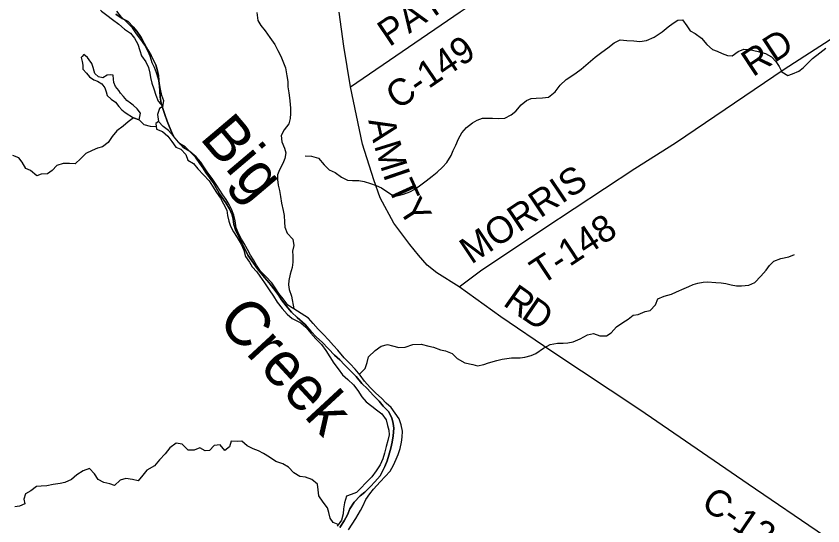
# Model space of a CAD drawing. Extents: x 114843 to 284848, y 317643 to 566895.
# Drawn here: x 132825 to 141921, y 394917 to 400664 of the extents above; entities that cross this region are included whole.
import ezdxf

# ---------------------------------------------------------------- set-up
doc = ezdxf.new("R2010")
doc.units = 0
for name, color, linetype in [('GM_X_County', 7, 'Continuous'), ('GM_X_County_Road', 7, 'Continuous'), ('GM_X_County_Road_Text', 7, 'Continuous'), ('GM_X_Major_River', 7, 'Continuous'), ('GM_X_Major_River_Text', 7, 'Continuous'), ('GM_X_Minor_Lake', 7, 'Continuous'), ('GM_X_Minor_River', 7, 'Continuous'), ('GM_X_Township', 7, 'Continuous'), ('GM_X_Township_Road', 7, 'Continuous'), ('GM_X_Township_Road_Text', 7, 'Continuous')]:
    doc.layers.add(name, color=color, linetype=linetype)

msp = doc.modelspace()

# ---------------------------------------------------------------- linework, layer by layer
at = {"layer": 'GM_X_County'}
for points in [[(133950.4, 400685.6), (134020.3, 400638.9), (134086.2, 400602.2), (134143.9, 400543.5), (134185.6, 400493), (134233.1, 400422.4), (134268.7, 400359.8), (134308.2, 400285.3), (134347.7, 400218.7), (134375.4, 400166.3), (134399, 400113.9), (134414.6, 400061.6), (134428.1, 399995.2), (134435.6, 399937), (134441.1, 399874.7), (134444.6, 399822.5), (134448, 399750.2), (134459.5, 399681.8), (134477, 399621.5), (134502.5, 399555), (134527.9, 399478.5), (134551.5, 399424.1), (134579, 399351.7), (134610.6, 399293.2), (134666.2, 399228.5), (134732.1, 399189.8), (134787.8, 399135.2), (134847.5, 399072.5), (134897.1, 399003.8), (134934.4, 398951.7), (134964.5, 398900.7), (135044.8, 398787.2), (135118.4, 398662), (135188.6, 398558.3), (135230.5, 398490.9), (135259.1, 398423.2), (135272.7, 398373.7), (135279.7, 398314.3), (135301.7, 398245), (135378.9, 398092.5), (135437.7, 397970.6), (135546.3, 397815.9), (135626.5, 397715.7), (135678, 397656.6), (135731.6, 397589.9), (135779.2, 397525.3), (135816.8, 397464.7), (135870.4, 397398.1), (135928, 397327.3), (135993.7, 397266.6), (136083.3, 397188.3), (136147.7, 397112.1), (136212.2, 397046), (136276.6, 396988), (136345.1, 396913.8), (136415.5, 396841.7), (136473.9, 396787.7), (136526.3, 396731.6), (136596.7, 396659.5), (136657.2, 396599.4), (136723.6, 396521.3), (136786, 396461.2), (136850.5, 396391), (136918.9, 396321), (136961.2, 396266.8), (137023.6, 396204.7), (137059.9, 396136.6), (137076.1, 396070.4), (137082.2, 396018.2), (137076.2, 395931.8), (137064.3, 395861.5), (137050.3, 395793.3), (137028.3, 395714.9), (137008.2, 395650.6), (136982.2, 395584.3), (136956.1, 395532), (136928, 395479.8), (136867.8, 395411.4), (136819.6, 395359), (136755.3, 395296.6), (136705.1, 395256.4), (136634.8, 395183.9), (136586.6, 395107.5), (136560.5, 395041.2), (136524.4, 394972.9), (136476.3, 394896.5)], [(136476.3, 394896.5), (136524.4, 394972.9), (136560.5, 395041.2), (136586.6, 395107.5), (136634.8, 395183.9), (136705.1, 395256.4), (136755.3, 395296.6), (136819.6, 395359), (136867.8, 395411.4), (136928, 395479.8), (136956.1, 395532), (136982.2, 395584.3), (137008.2, 395650.6), (137028.3, 395714.9), (137050.3, 395793.3), (137064.3, 395861.5), (137076.2, 395931.8), (137082.2, 396018.2), (137076.1, 396070.4), (137059.9, 396136.6), (137023.6, 396204.7), (136961.2, 396266.8), (136918.9, 396321), (136850.5, 396391), (136786, 396461.2), (136723.6, 396521.3), (136657.2, 396599.4), (136596.7, 396659.5), (136526.3, 396731.6), (136473.9, 396787.7), (136415.5, 396841.7), (136345.1, 396913.8), (136276.6, 396988), (136212.2, 397046), (136147.7, 397112.1), (136083.3, 397188.3), (135993.7, 397266.6), (135928, 397327.3), (135870.4, 397398.1), (135816.8, 397464.7), (135779.2, 397525.3), (135731.6, 397589.9), (135678, 397656.6), (135626.5, 397715.7), (135546.3, 397815.9), (135437.7, 397970.6), (135378.9, 398092.5), (135301.7, 398245), (135279.7, 398314.3), (135272.7, 398373.7), (135259.1, 398423.2), (135230.5, 398490.9), (135188.6, 398558.3), (135118.4, 398662), (135044.8, 398787.2), (134964.5, 398900.7), (134934.4, 398951.7), (134897.1, 399003.8), (134847.5, 399072.5), (134787.8, 399135.2), (134732.1, 399189.8), (134666.2, 399228.5), (134610.6, 399293.2), (134579, 399351.7), (134551.5, 399424.1), (134527.9, 399478.5), (134502.5, 399555), (134477, 399621.5), (134459.5, 399681.8), (134448, 399750.2), (134444.6, 399822.5), (134441.1, 399874.7), (134435.6, 399937), (134428.1, 399995.2), (134414.6, 400061.6), (134399, 400113.9), (134375.4, 400166.3), (134347.7, 400218.7), (134308.2, 400285.3), (134268.7, 400359.8), (134233.1, 400422.4), (134185.6, 400493), (134143.9, 400543.5), (134086.2, 400602.2), (134020.3, 400638.9), (133950.4, 400685.6)]]:
    msp.add_lwpolyline(points, dxfattribs=at)
at = {"layer": 'GM_X_County_Road'}
for points in [[(136594.3, 399866), (137829.4, 400711.5), (141179, 402947.6), (141215, 402965.7), (141241.1, 402967.7), (141261.1, 402963.7), (141281.1, 402951.7), (141313.1, 402913.6), (141487.4, 402620.9), (141509.4, 402586.8), (141529.5, 402576.8), (141559.5, 402580.9), (141689.6, 402661.2), (144712.9, 404666.2), (146657, 405975.2)], [(141938.1, 394800.8), (141080, 395387.2), (139857.3, 396226.3), (138865.5, 396883.5), (138291.1, 397274.8), (137819, 397611.5), (137569.2, 397769.1), (137460.2, 397857.6), (137361.7, 397967.5), (137265.2, 398087.9), (137083.9, 398327.9), (136928.8, 398615.9), (136859.3, 398819.5), (136731.5, 399219.5), (136594.3, 399866), (136518.1, 400325), (136466.8, 400710.6)]]:
    msp.add_lwpolyline(points, dxfattribs=at)
at = {"layer": 'GM_X_Major_River'}
for points in [[(133775.9, 400731.6), (133787.3, 400721), (133848.4, 400673.6), (133912, 400627.1), (133983.6, 400572.4), (134047.1, 400515.9), (134112.8, 400473.3), (134160.4, 400416.9), (134197.8, 400346.5), (134219.3, 400278.2), (134238.8, 400215.9), (134288.2, 400149.4), (134315.7, 400085.1), (134333.2, 400020.9), (134340.8, 399970.7), (134356.3, 399908.5), (134377.8, 399844.2), (134401.3, 399773.9), (134426.7, 399705.6), (134478.3, 399645.1)], [(134478.3, 399645.1), (134490.8, 399709.2), (134467.2, 399769.4), (134453.8, 399839.7), (134442.3, 399903.9), (134428.7, 399954), (134407.3, 400026.3), (134383.7, 400086.6), (134360.1, 400136.9), (134336.7, 400211.2), (134309.2, 400271.5), (134275.7, 400335.9), (134232.2, 400402.3), (134180.7, 400462.8), (134137.3, 400533.2), (134075.8, 400593.8), (134012.2, 400652.4), (133960.8, 400720.9)], [(134478.3, 399645.1), (134442.1, 399623.4), (134417.5, 399553.4), (134428.9, 399475.2)], [(134428.9, 399475.2), (134398.8, 399455.4)], [(134398.8, 399455.4), (134406.2, 399389.2), (134474, 399362.7), (134535.6, 399312.1), (134581.1, 399251.7), (134626.6, 399185.2), (134682.4, 399162.8), (134738, 399104.3), (134761.5, 399040), (134823.2, 399003.4), (134872.7, 398941), (134936.2, 398876.4), (135001.6, 398807.8), (135037.1, 398747.4), (135084.6, 398674.9), (135128, 398610.5), (135163.5, 398546.1), (135199, 398477.7), (135208.5, 398415.5), (135224, 398351.3), (135241.6, 398297.1), (135275, 398230.7), (135316.5, 398168.3), (135363.9, 398091.8), (135391.4, 398023.5), (135410.9, 397955.2), (135456.3, 397888.8), (135487.9, 397838.5), (135539.5, 397782), (135571.1, 397731.6), (135624.5, 397657.1), (135677.9, 397578.6), (135725.3, 397508.1), (135766.7, 397437.7), (135824.2, 397369.1), (135881.7, 397304.6), (135935.3, 397256.1), (136033.5, 397207.5)], [(136119.6, 397259.4), (135954.2, 397364.2), (135886.5, 397406.7), (135835, 397475.2), (135787.5, 397537.7), (135746, 397600.1), (135706.5, 397656.5), (135645, 397723.1), (135581.5, 397789.7), (135534.1, 397856.1), (135500.5, 397914.5), (135467, 397970.8), (135433.5, 398033.2), (135396, 398099.6), (135366.4, 398149.9), (135336.8, 398206.2), (135307.4, 398278.6), (135294, 398354.8), (135280.5, 398419), (135253.1, 398487.3), (135225.5, 398539.6), (135191.9, 398598), (135154.4, 398650.4), (135122.8, 398700.7), (135089.2, 398755), (135035.8, 398831.6), (134986.3, 398898), (134940.8, 398964.5), (134907.3, 399016.8), (134853.8, 399079.4), (134784.2, 399136), (134712.6, 399178.6), (134655.1, 399243.1), (134597.6, 399309.7), (134544.1, 399376.2), (134482.5, 399420.7), (134428.9, 399475.2)], [(136570.9, 394872.4), (136655.1, 394998.4), (136707.3, 395088.4), (136733.4, 395140.4), (136767.6, 395212.5), (136811.7, 395276.5), (136855.8, 395330.5), (136929.9, 395412.5), (136986, 395474.5), (137042.2, 395532.5), (137078.3, 395600.5), (137108.4, 395668.5), (137130.5, 395720.6), (137154.6, 395790.6), (137170.8, 395858.7), (137178.9, 395918.7), (137181, 395984.8), (137167.2, 396056.9), (137145.3, 396123), (137097.4, 396189.1), (137053.5, 396251.2), (136995.6, 396301.3), (136943.8, 396355.5), (136881.9, 396413.6), (136818, 396475.7), (136754.1, 396549.9), (136704.3, 396616), (136646.4, 396682.2), (136592.5, 396742.3), (136522.7, 396812.5), (136452.8, 396896.6), (136404.9, 396950.8), (136345.1, 397014.9), (136291.2, 397073), (136231.3, 397133.2), (136175.4, 397197.3), (136119.6, 397259.4)], [(136033.5, 397207.5), (136091.4, 397155.4), (136147.2, 397089.2), (136205.1, 397027.1), (136269, 396962.9), (136316.8, 396892.8), (136408.6, 396752.6), (136454.4, 396688.4), (136506.3, 396620.3), (136566.2, 396566.2), (136628.1, 396506), (136675.9, 396441.9), (136723.8, 396369.8), (136771.7, 396315.6), (136835.6, 396265.5), (136887.5, 396223.4), (136949.4, 396179.3), (136995.3, 396111.1), (137013.1, 396047), (137025.1, 395997), (137030.9, 395944.9), (137016.8, 395878.9), (136996.7, 395810.8), (136978.6, 395736.8), (136960.4, 395670.7), (136928.3, 395606.7), (136884.2, 395538.7), (136836.1, 395468.7), (136763.9, 395396.7), (136713.8, 395346.7), (136663.7, 395294.7), (136601.7, 395268.7), (136549.7, 395250.8), (136527.5, 395174.7), (136515.4, 395108.7), (136511.3, 395052.6), (136495.1, 394982.6), (136443, 394912.6)]]:
    msp.add_lwpolyline(points, dxfattribs=at)
at = {"layer": 'GM_X_Minor_Lake'}
msp.add_line((134147.8, 399516.3), (134211.8, 399496.2), dxfattribs=at)
for points in [[(134211.8, 399496.2), (134227.8, 399570.3), (134189.9, 399620.4), (134145.9, 399660.5), (134115.9, 399682.5), (134074, 399714.6), (134036, 399756.7), (134000.1, 399796.7), (133982.1, 399826.8), (133946.2, 399870.9), (133926.2, 399914.9), (133922.2, 399955), (133920.2, 399997.1), (133892.3, 400001.1), (133850.3, 399999.1), (133802.3, 399967.1), (133752.3, 399981.1), (133712.4, 400017.2), (133704.4, 400043.2), (133694.4, 400085.3), (133678.5, 400129.3), (133648.5, 400171.4), (133630.5, 400199.5), (133586.6, 400231.5), (133567.9, 400210.1)], [(133567.9, 400210.1), (133558.6, 400199.5), (133570.5, 400151.4), (133576.5, 400111.4), (133578.5, 400067.3), (133616.4, 400021.2), (133650.4, 399979.1), (133702.3, 399947.1), (133742.3, 399931), (133792.3, 399899), (133826.2, 399856.9), (133840.2, 399810.8), (133850.1, 399770.8), (133898.1, 399728.7), (133944, 399694.6), (133982, 399646.5), (134015.9, 399606.5), (134055.9, 399578.4), (134147.8, 399516.3)], [(134478.3, 399645.1), (134442.1, 399623.4), (134417.5, 399553.4), (134428.9, 399475.2)]]:
    msp.add_lwpolyline(points, dxfattribs=at)
at = {"layer": 'GM_X_Minor_River'}
for points in [[(135537.9, 400706.4), (135550.2, 400614.4), (135582.1, 400560.2), (135631.9, 400499.9), (135683.7, 400421.6), (135743.5, 400345.3), (135777.3, 400277.1), (135811.1, 400212.8), (135840.9, 400136.6), (135862.7, 400082.4), (135878.5, 399992.2), (135888.3, 399928), (135888.1, 399867.9), (135897.9, 399797.7), (135905.8, 399743.6), (135915.6, 399671.4), (135917.4, 399621.3), (135917.3, 399567.1), (135913.1, 399511), (135898.9, 399450.9), (135846.7, 399380.9), (135814.6, 399316.8), (135822.4, 399248.6), (135850.2, 399174.4), (135866, 399122.2), (135855.8, 399058.1), (135833.7, 399004.1), (135793.5, 398930), (135773.3, 398875.9), (135773.2, 398823.8), (135781, 398759.6), (135792.8, 398699.4), (135804.6, 398631.3), (135818.4, 398557.1), (135836.2, 398470.8), (135846, 398416.7), (135849.8, 398340.5), (135853.7, 398286.4), (135879.5, 398218.2), (135943.3, 398147.8), (135955.1, 398077.7), (135940.9, 398013.5), (135942.7, 397961.4), (135944.5, 397891.3), (135936.4, 397831.1), (135914.2, 397755), (135900, 397684.9), (135895.8, 397632.8), (135903.7, 397580.7), (135929.5, 397506.4), (135954.2, 397364.2)], [(136083, 399087.7), (136155, 399083.5), (136235, 399061.1), (136298.6, 398986.8), (136354.4, 398930.5), (136422.3, 398900.2), (136492.1, 398847.9), (136559.9, 398813.6), (136615.9, 398809.3), (136689.9, 398809.1), (136749.9, 398800.8), (136821.8, 398778.5), (136885.7, 398756.3), (136943.6, 398730), (137005.5, 398687.7), (137057.3, 398651.5), (137115.3, 398639.2), (137193.3, 398655), (137265.5, 398682.7), (137319.7, 398714.6), (137371.8, 398750.4), (137446.1, 398806.2), (137516.3, 398858), (137572.5, 398905.9), (137632.8, 398959.7), (137679.1, 399015.6), (137729.4, 399091.5), (137751.7, 399149.5), (137781.9, 399209.5), (137812.2, 399279.5), (137848.6, 399347.4), (137900.8, 399409.3), (137971.1, 399461.1), (138021.2, 399491), (138083.3, 399512.8), (138145.4, 399514.5), (138197.4, 399514.3), (138265.4, 399510.1), (138335.4, 399513.8), (138405.6, 399549.6), (138457.8, 399593.5), (138520.1, 399663.3), (138580.3, 399711.2), (138632.4, 399735), (138688.5, 399738.8), (138758.5, 399742.5), (138828.5, 399752.3), (138900.8, 399810.1), (138957.2, 399884), (139025.5, 399949.8), (139079.6, 399981.7), (139139.8, 400023.5), (139194, 400065.3), (139276.3, 400133.1), (139354.7, 400202.9), (139428.9, 400256.7), (139497.2, 400308.5), (139569.4, 400362.3), (139635.6, 400398.1), (139711.6, 400389.8), (139787.5, 400385.5), (139857.5, 400377.3), (139931.6, 400391), (140017.8, 400428.7), (140108.1, 400486.5), (140178.3, 400542.3), (140232.5, 400586.1), (140286.7, 400620), (140338.7, 400621.8), (140386.4, 400553.5), (140424.2, 400499.3), (140482.1, 400467), (140553.8, 400416.7), (140611.5, 400344.4), (140677.3, 400286.1), (140729.2, 400269.8), (140785.1, 400241.6), (140845, 400219.3), (140897, 400215.1), (140967.3, 400266.9), (141031.4, 400292.7), (141093.4, 400286.5), (141191.3, 400266.1), (141273.2, 400243.7), (141343.1, 400203.4), (141390.8, 400151.2), (141428.6, 400097), (141458.3, 400036.8), (141526.2, 399994.4), (141578.3, 400012.3), (141648.4, 400044.1), (141698.6, 400081.9), (141752.8, 400133.8), (141805.1, 400185.6), (141887.4, 400249.4), (141955.6, 400301.2)], [(134403.4, 399414.5), (134339.6, 399420.1), (134267.7, 399440.1), (134211.8, 399496.2), (134147.8, 399516.3), (134089.8, 399474.2), (134031.8, 399422.2), (133961.8, 399370.1), (133907.8, 399306), (133863.8, 399240), (133799.8, 399191.9), (133743.8, 399173.9), (133681.9, 399147.9), (133609.9, 399115.8), (133553.9, 399059.8), (133491.9, 398999.7), (133425.9, 399001.7), (133354, 399001.8), (133284, 398981.8), (133230, 398923.7), (133180, 398887.7), (133108, 398883.7), (133058, 398863.7), (132988.1, 398921.8), (132934.2, 398947.8), (132894.2, 399015.9), (132856.3, 399068), (132786.3, 399092.1)], [(136695.4, 396626.1), (136760.6, 396689.9), (136780.9, 396757.9), (136797.2, 396822), (136873.5, 396895.8), (136941.7, 396943.6), (137011.8, 396961.4), (137069.7, 396945.1), (137139.7, 396926.8), (137209.7, 396932.6), (137297.9, 396960.3), (137389.9, 396963.9), (137479.8, 396943.6), (137531.8, 396933.4), (137609.7, 396901), (137667.6, 396890.8), (137739.5, 396860.5), (137799.3, 396802.2), (137883.1, 396753.8), (137973, 396737.4), (138027, 396721.2), (138097, 396735), (138149.1, 396756.8), (138245.3, 396782.5), (138305.3, 396796.2), (138357.4, 396804.1), (138411.4, 396809.9), (138507.4, 396811.5), (138561.5, 396819.3), (138631.6, 396837.1), (138683.7, 396860.9), (138770, 396920.7), (138844.2, 396960.4), (138928.3, 396978.1), (138994.3, 396977.9), (139044.3, 396979.7), (139106.4, 396993.5), (139184.5, 397027.2), (139266.7, 397069), (139334.8, 397086.8), (139406.7, 397058.4), (139482.8, 397060.2), (139532.9, 397092), (139595.2, 397159.9), (139665.5, 397209.7), (139725.6, 397247.5), (139781.8, 397293.4), (139837.9, 397299.2), (139916, 397332.9), (139974.1, 397344.7), (140034.4, 397410.6), (140060.7, 397476.5), (140132.9, 397508.3), (140213, 397528), (140271.1, 397553.9), (140355.3, 397591.6), (140409.4, 397617.4), (140459.5, 397639.3), (140509.6, 397655.1), (140569.7, 397664.9), (140621.7, 397666.7), (140715.7, 397660.3), (140773.7, 397656.1), (140827.6, 397647.9), (140887.6, 397635.7), (140945.5, 397623.4), (141001.6, 397623.2), (141087.6, 397630.9), (141151.8, 397660.7), (141222.1, 397730.5), (141282.4, 397800.4), (141318.6, 397852.3), (141368.9, 397900.2), (141447, 397931.9), (141535.1, 397951.7), (141601.2, 397975.4)], [(136024.2, 395473.6), (135956.3, 395513.7), (135894.4, 395579.8), (135830.4, 395615.9), (135754.5, 395643.9), (135682.6, 395690), (135614.6, 395732.1), (135558.7, 395764.2), (135498.7, 395784.2), (135428.8, 395820.3), (135370.8, 395870.4), (135316.9, 395866.4), (135250.9, 395870.5), (135230.9, 395806.4), (135178.9, 395768.3), (135125, 395830.4), (135059, 395824.4), (135005, 395768.4), (134955, 395762.4), (134895.1, 395798.4), (134833.1, 395770.4), (134763.1, 395770.5), (134697.2, 395838.6), (134627.3, 395848.6), (134559.3, 395796.6), (134503.3, 395730.5), (134441.2, 395662.4), (134383.2, 395594.3), (134299.3, 395546.3), (134253.3, 395490.2), (134201.2, 395424.1), (134135.3, 395438.2), (134063.3, 395452.2), (133999.4, 395430.2), (133933.4, 395370.1), (133881.4, 395390.2), (133813.5, 395406.2), (133749.5, 395438.3), (133709.6, 395504.4), (133651.6, 395562.5), (133581.7, 395538.5), (133509.7, 395490.5), (133447.7, 395438.4), (133373.7, 395406.4), (133321.7, 395394.4), (133241.8, 395382.4), (133169.8, 395366.4), (133105.8, 395364.4), (133053.9, 395362.4), (132991.9, 395310.4), (132929.9, 395276.3), (132909.8, 395218.3), (132923.8, 395166.2), (132863.8, 395138.2), (132811.8, 395130.2)], [(136456.4, 394930.6), (136398.4, 394954.4), (136366.2, 395004.3), (136349.9, 395066.3), (136335.7, 395118.3), (136285.5, 395184.1), (136239.2, 395254), (136230.9, 395322), (136222.6, 395388), (136158.4, 395437.7), (136088.2, 395467.4), (136024.2, 395473.6)]]:
    msp.add_lwpolyline(points, dxfattribs=at)
at = {"layer": 'GM_X_Township'}
for points in [[(133950.4, 400685.6), (134020.3, 400638.9), (134086.2, 400602.2), (134143.9, 400543.5), (134185.6, 400493), (134233.1, 400422.4), (134268.7, 400359.8), (134308.2, 400285.3), (134347.7, 400218.7), (134375.4, 400166.3), (134399, 400113.9), (134414.6, 400061.6), (134428.1, 399995.2), (134435.6, 399937), (134441.1, 399874.7), (134444.6, 399822.5), (134448, 399750.2), (134459.5, 399681.8), (134477, 399621.5), (134502.5, 399555), (134527.9, 399478.5), (134551.5, 399424.1), (134579, 399351.7), (134610.6, 399293.2), (134666.2, 399228.5), (134732.1, 399189.8), (134787.8, 399135.2), (134847.5, 399072.5), (134897.1, 399003.8), (134934.4, 398951.7), (134964.5, 398900.7), (135044.8, 398787.2), (135118.4, 398662), (135188.6, 398558.3), (135230.5, 398490.9), (135259.1, 398423.2), (135272.7, 398373.7), (135279.7, 398314.3), (135301.7, 398245), (135378.9, 398092.5), (135437.7, 397970.6), (135546.3, 397815.9), (135626.5, 397715.7), (135678, 397656.6), (135731.6, 397589.9), (135779.2, 397525.3), (135816.8, 397464.7), (135870.4, 397398.1), (135928, 397327.3), (135993.7, 397266.6), (136083.3, 397188.3), (136147.7, 397112.1), (136212.2, 397046), (136276.6, 396988), (136345.1, 396913.8), (136415.5, 396841.7), (136473.9, 396787.7), (136526.3, 396731.6), (136596.7, 396659.5), (136657.2, 396599.4), (136723.6, 396521.3), (136786, 396461.2), (136850.5, 396391), (136918.9, 396321), (136961.2, 396266.8), (137023.6, 396204.7), (137059.9, 396136.6), (137076.1, 396070.4), (137082.2, 396018.2), (137076.2, 395931.8), (137064.3, 395861.5), (137050.3, 395793.3), (137028.3, 395714.9), (137008.2, 395650.6), (136982.2, 395584.3), (136956.1, 395532), (136928, 395479.8), (136867.8, 395411.4), (136819.6, 395359), (136755.3, 395296.6), (136705.1, 395256.4), (136634.8, 395183.9), (136586.6, 395107.5), (136560.5, 395041.2), (136524.4, 394972.9), (136476.3, 394896.5)], [(136476.3, 394896.5), (136524.4, 394972.9), (136560.5, 395041.2), (136586.6, 395107.5), (136634.8, 395183.9), (136705.1, 395256.4), (136755.3, 395296.6), (136819.6, 395359), (136867.8, 395411.4), (136928, 395479.8), (136956.1, 395532), (136982.2, 395584.3), (137008.2, 395650.6), (137028.3, 395714.9), (137050.3, 395793.3), (137064.3, 395861.5), (137076.2, 395931.8), (137082.2, 396018.2), (137076.1, 396070.4), (137059.9, 396136.6), (137023.6, 396204.7), (136961.2, 396266.8), (136918.9, 396321), (136850.5, 396391), (136786, 396461.2), (136723.6, 396521.3), (136657.2, 396599.4), (136596.7, 396659.5), (136526.3, 396731.6), (136473.9, 396787.7), (136415.5, 396841.7), (136345.1, 396913.8), (136276.6, 396988), (136212.2, 397046), (136147.7, 397112.1), (136083.3, 397188.3), (135993.7, 397266.6), (135928, 397327.3), (135870.4, 397398.1), (135816.8, 397464.7), (135779.2, 397525.3), (135731.6, 397589.9), (135678, 397656.6), (135626.5, 397715.7), (135546.3, 397815.9), (135437.7, 397970.6), (135378.9, 398092.5), (135301.7, 398245), (135279.7, 398314.3), (135272.7, 398373.7), (135259.1, 398423.2), (135230.5, 398490.9), (135188.6, 398558.3), (135118.4, 398662), (135044.8, 398787.2), (134964.5, 398900.7), (134934.4, 398951.7), (134897.1, 399003.8), (134847.5, 399072.5), (134787.8, 399135.2), (134732.1, 399189.8), (134666.2, 399228.5), (134610.6, 399293.2), (134579, 399351.7), (134551.5, 399424.1), (134527.9, 399478.5), (134502.5, 399555), (134477, 399621.5), (134459.5, 399681.8), (134448, 399750.2), (134444.6, 399822.5), (134441.1, 399874.7), (134435.6, 399937), (134428.1, 399995.2), (134414.6, 400061.6), (134399, 400113.9), (134375.4, 400166.3), (134347.7, 400218.7), (134308.2, 400285.3), (134268.7, 400359.8), (134233.1, 400422.4), (134185.6, 400493), (134143.9, 400543.5), (134086.2, 400602.2), (134020.3, 400638.9), (133950.4, 400685.6)]]:
    msp.add_lwpolyline(points, dxfattribs=at)
at = {"layer": 'GM_X_Township_Road'}
msp.add_lwpolyline([(137819, 397611.5), (138062.1, 397793.9), (138774.8, 398271), (139799.5, 398946.9), (140259.2, 399234), (141483.5, 400068), (142288.4, 400586.6)], dxfattribs=at)

# ---------------------------------------------------------------- texts
at = {"layer": 'GM_X_County_Road_Text'}
for s, height, rotation, p in [('PATTERSON', 300.01, 33.90409, (137032.1, 400312.3)), ('C-149', 300.01, 34.2545, (137125.2, 399601.8)), ('A', 300, 282.40743, (136794.3, 399489.3)), ('M', 300, 287.24634, (136858.1, 399204.8)), ('I', 300, 288.85259, (136957.4, 398885.1)), ('T', 300, 294.51396, (137009.2, 398738.4)), ('Y', 300, 302.91619, (137125.4, 398492.1)), ('R', 300, 324.77171, (138301.4, 397411.6)), ('D', 300, 325.7759, (138507.3, 397266.2)), ('C-12', 300.02, 325.86732, (140532.9, 395130.6))]:
    msp.add_text(s, height=height, rotation=rotation, dxfattribs=at).set_placement(p)
at = {"layer": 'GM_X_Major_River_Text'}
for s, rotation, p in [('Big', 310.2459, (134885.1, 399287.3)), ('Creek', 312.70076, (135079, 397214.3))]:
    msp.add_text(s, height=499.98, rotation=rotation, dxfattribs=at).set_placement(p)
at = {"layer": 'GM_X_Township_Road_Text'}
for s, rotation, p in [('RD', 33.41425, (141131.7, 399972.4)), ('MORRIS', 33.85483, (137957, 397859.7)), ('T-148', 33.40025, (138748.5, 397625.7))]:
    msp.add_text(s, height=300.01, rotation=rotation, dxfattribs=at).set_placement(p)

doc.saveas('drawing.dxf')
